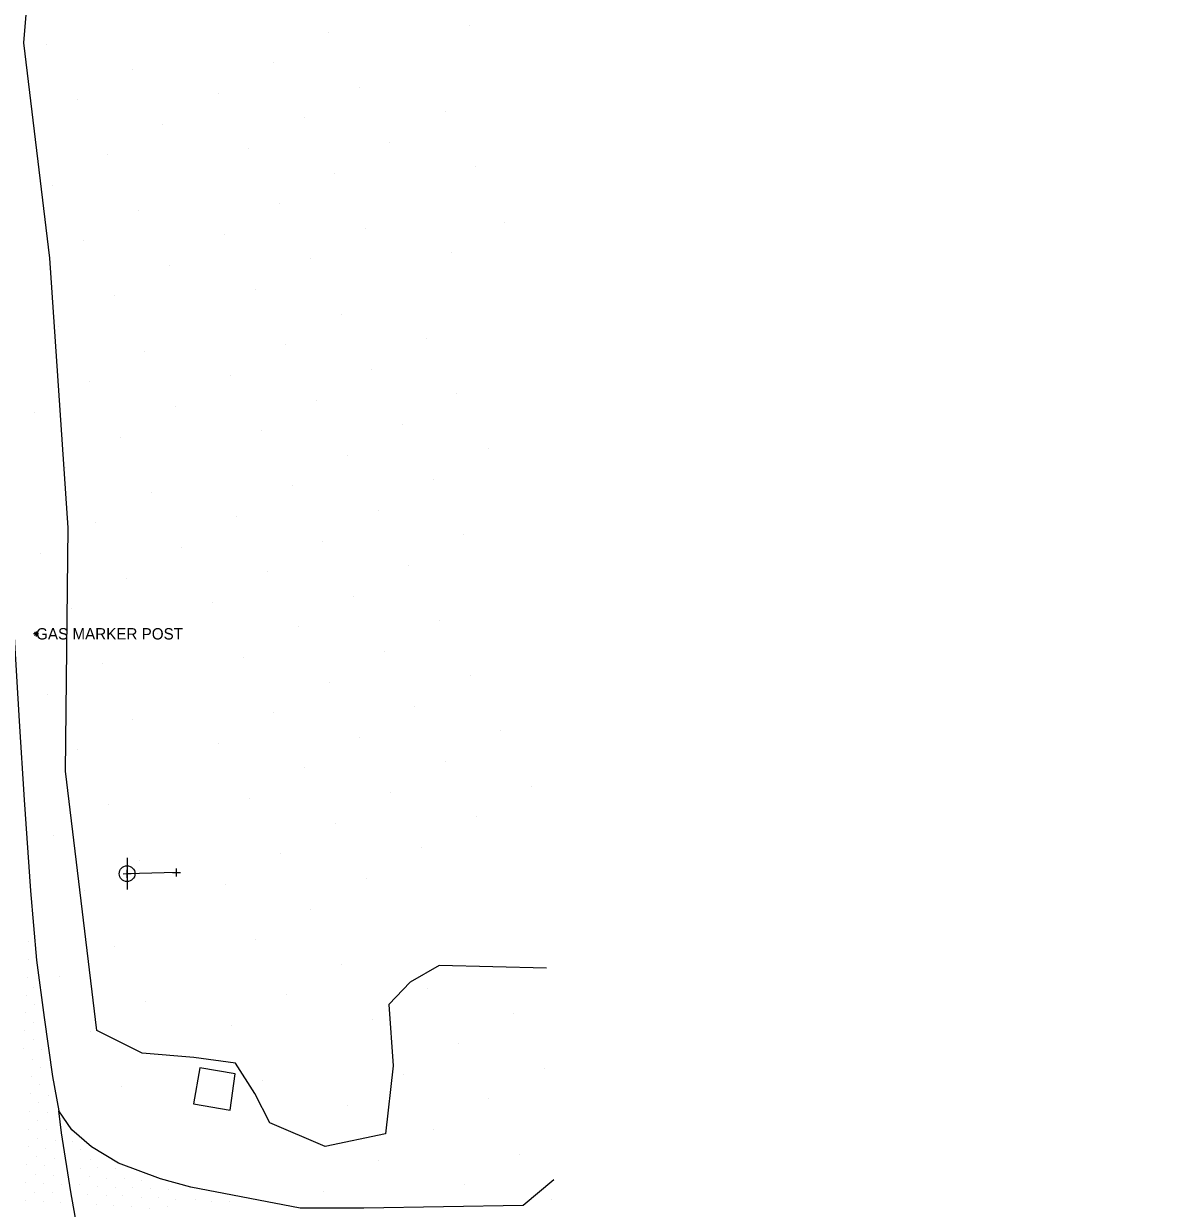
# Model space of a CAD drawing. Extents: x 1733582 to 1734070, y 467256 to 468256.
# Drawn here: x 1733851.7 to 1734031.3, y 467368 to 467555.7 of the extents above; entities that cross this region are included whole.
import ezdxf

# ---------------------------------------------------------------- set-up
doc = ezdxf.new("R2010")
doc.units = 0
for name, color, linetype in [('Default', 7, 'Continuous'), ('S_Ground_LevelString', 7, 'Continuous'), ('S_Ground_SpotElevation', 7, 'Continuous'), ('S_Misc_MiscItems', 7, 'Continuous'), ('S_Roadway_Drive_Paved', 7, 'Continuous'), ('S_Roadway_Edge_Pavement', 7, 'Continuous'), ('S_Survey_Shot', 7, 'Continuous'), ('S_Text', 7, 'Continuous'), ('S_Trees_Bush_Line', 7, 'Continuous'), ('S_Utilities_GuyWire3', 7, 'Continuous'), ('S_Utilities_Pole_Power', 7, 'Continuous')]:
    doc.layers.add(name, color=color, linetype=linetype)

# ---------------------------------------------------------------- blocks, each defined once
blk = doc.blocks.new('POINT_DISPLAY')
at = {"layer": 'Default'}
blk.add_line((0, 0), (0, 0), dxfattribs=at)

msp = doc.modelspace()

# ---------------------------------------------------------------- linework, layer by layer
at = {"layer": 'S_Ground_LevelString'}
msp.add_lwpolyline([(1733885.2, 467389.3), (1733879.61, 467390.29), (1733878.63, 467384.56), (1733884.43, 467383.56), (1733885.2, 467389.3)], dxfattribs=at)
at = {"layer": 'S_Misc_MiscItems'}
for p, q in [((1733854.07, 467459.02), (1733853.28, 467459.02)), ((1733853.94, 467458.75), (1733853.41, 467459.28)), ((1733853.94, 467459.28), (1733853.41, 467458.75)), ((1733853.68, 467459.41), (1733853.68, 467458.62))]:
    msp.add_line(p, q, dxfattribs=at)
at = {"layer": 'S_Roadway_Drive_Paved'}
msp.add_lwpolyline([(1733935.69, 467372.52), (1733930.85, 467368.48), (1733905.61, 467368.04), (1733895.53, 467368.04), (1733878.21, 467371.35), (1733873.41, 467372.67), (1733866.75, 467375.19), (1733862.45, 467377.76), (1733859.35, 467380.43), (1733857.26, 467383.48)], dxfattribs=at)
at = {"layer": 'S_Roadway_Edge_Pavement'}
for points in [[(1733844.86, 467556.39), (1733844.81, 467544.75), (1733845.09, 467538.7), (1733845.54, 467531.94), (1733846.9, 467523.49), (1733847.19, 467517.58), (1733848.33, 467507.5), (1733848.82, 467501.93), (1733849.37, 467495.51), (1733849.25, 467489.25), (1733848.88, 467482.09), (1733849.39, 467470.34), (1733850.19, 467458.56), (1733850.99, 467445.17), (1733851.8, 467432.75), (1733852.77, 467418.3), (1733853.74, 467407.33), (1733854.98, 467398.25), (1733856.26, 467388.9), (1733857.26, 467383.48)], [(1733865.37, 467333.83), (1733864.02, 467343.01), (1733861.67, 467356.68), (1733859.17, 467370.65), (1733857.7, 467379.97), (1733857.26, 467383.48)]]:
    msp.add_lwpolyline(points, dxfattribs=at)
at = {"layer": 'S_Survey_Shot'}
for p, q in [((1733867.46, 467421.02), (1733868.73, 467421.03)), ((1733868.1, 467420.39), (1733868.09, 467421.66)), ((1733868.09, 467421.02), (1733868.09, 467421.02)), ((1733875.28, 467421.2), (1733876.55, 467421.2)), ((1733875.92, 467420.56), (1733875.91, 467421.84)), ((1733875.92, 467421.2), (1733875.92, 467421.2))]:
    msp.add_line(p, q, dxfattribs=at)
at = {"layer": 'S_Trees_Bush_Line'}
for points in [[(1733870.48, 467392.59), (1733863.3, 467396.17), (1733858.35, 467437.26), (1733858.75, 467475.79), (1733855.85, 467518.53), (1733851.72, 467552.62), (1733854.12, 467581.29), (1733854.36, 467608.62), (1733855, 467643.49), (1733857.77, 467661.2), (1733862.91, 467670.92), (1733887.36, 467667.82), (1733924.77, 467650.09), (1734031.29, 467613.46)], [(1733934.51, 467406.04), (1733917.54, 467406.47), (1733912.96, 467403.85), (1733909.54, 467400.28), (1733910.22, 467390.61), (1733909.03, 467379.81), (1733899.45, 467377.84), (1733890.7, 467381.58), (1733888.33, 467386.19), (1733885.25, 467391.01), (1733878.64, 467391.93), (1733870.48, 467392.59)]]:
    msp.add_lwpolyline(points, dxfattribs=at)
at = {"layer": 'S_Utilities_GuyWire3'}
msp.add_lwpolyline([(1733875.92, 467421.2), (1733868.09, 467421.02)], dxfattribs=at)
at = {"layer": 'S_Utilities_Pole_Power'}
msp.add_line((1733868.09, 467423.52), (1733868.09, 467418.53), dxfattribs=at)
msp.add_circle((1733868.09, 467421.02), 1.25, dxfattribs=at)

# ---------------------------------------------------------------- block references
at = {"layer": 'S_Ground_SpotElevation'}
for p in [(1733899.99, 467554.33), (1733922.33, 467555.32), (1733855.32, 467552.34), (1733868.92, 467548.47), (1733891.26, 467549.46), (1733882.52, 467544.6), (1733904.86, 467545.59), (1733860.18, 467543.61), (1733896.12, 467540.73), (1733918.46, 467541.72), (1733873.78, 467539.73), (1733887.38, 467535.86), (1733909.72, 467536.86), (1733865.05, 467534.87), (1733900.99, 467531.99), (1733923.32, 467532.98), (1733856.31, 467530), (1733869.91, 467526.13), (1733892.25, 467527.13), (1733927.91, 467524.24), (1733883.51, 467522.26), (1733905.85, 467523.25), (1733861.17, 467521.27), (1733897.11, 467518.39), (1733919.45, 467519.38), (1733874.78, 467517.4), (1733866.04, 467512.53), (1733888.38, 467513.52), (1733901.98, 467509.65), (1733857.3, 467507.67), (1733915.58, 467505.78), (1733870.9, 467503.79), (1733893.24, 467504.79), (1733884.51, 467499.92), (1733906.84, 467500.92), (1733862.17, 467498.93), (1733898.11, 467496.05), (1733920.31, 467497.14), (1733853.43, 467494.06), (1733875.77, 467495.06), (1733911.71, 467492.18), (1733867.03, 467490.19), (1733889.37, 467491.19), (1733925.31, 467488.31), (1733902.97, 467487.31), (1733858.29, 467485.33), (1733916.57, 467483.44), (1733871.9, 467481.46), (1733894.24, 467482.45), (1733885.5, 467477.58), (1733907.84, 467478.58), (1733863.16, 467476.59), (1733899.1, 467473.71), (1733921.44, 467474.71), (1733854.42, 467471.73), (1733876.76, 467472.72), (1733912.7, 467469.84), (1733868.02, 467467.85), (1733890.36, 467468.85), (1733881.63, 467463.98), (1733903.97, 467464.98), (1733859.29, 467462.99), (1733895.23, 467460.11), (1733917.57, 467461.1), (1733872.89, 467459.12), (1733908.83, 467456.24), (1733886.49, 467455.25), (1733864.15, 467454.25), (1733900.09, 467451.37), (1733922.43, 467452.37), (1733855.42, 467449.39), (1733913.7, 467447.5), (1733869.02, 467445.52), (1733891.36, 467446.51), (1733927.3, 467443.63), (1733882.62, 467441.64), (1733904.96, 467442.64), (1733860.28, 467440.65), (1733896.22, 467437.77), (1733918.56, 467438.76), (1733909.82, 467433.9), (1733932.16, 467434.89), (1733865.15, 467431.91), (1733887.48, 467432.91), (1733923.43, 467430.03), (1733901.09, 467429.03), (1733856.41, 467427.05), (1733914.69, 467425.16), (1733870.01, 467423.18), (1733892.35, 467424.17), (1733883.61, 467419.3), (1733905.95, 467420.3), (1733861.27, 467418.31), (1733897.21, 467415.43), (1733852.45, 467410.34), (1733866.14, 467409.57), (1733888.48, 467410.57), (1733852.44, 467407.39), (1733902.08, 467406.7), (1733852.32, 467404.52), (1733857.4, 467404.71), (1733853.29, 467403.07), (1733893.34, 467401.83), (1733915.68, 467402.82), (1733852.18, 467401.75), (1733853.45, 467400.36), (1733871, 467400.84), (1733852.04, 467398.97), (1733929.28, 467398.95), (1733851.9, 467396.17), (1733853.23, 467397.49), (1733884.61, 467396.97), (1733906.94, 467397.96), (1733853.21, 467394.73), (1733862.27, 467395.97), (1733851.74, 467393.38), (1733854.56, 467393.19), (1733920.55, 467394.09), (1733853.06, 467391.67), (1733875.87, 467392.1), (1733852.92, 467388.96), (1733854.41, 467390.39), (1733911.81, 467389.22), (1733934.15, 467390.22), (1733854.2, 467387.65), (1733867.13, 467387.24), (1733889.47, 467388.23), (1733852.74, 467386.24), (1733855.64, 467385.92), (1733925.41, 467385.35), (1733852.68, 467383.3), (1733854.09, 467384.82), (1733855.44, 467383.14), (1733903.07, 467384.36), (1733853.84, 467381.96), (1733852.51, 467380.52), (1733855.31, 467380.52), (1733916.67, 467380.49), (1733852.4, 467377.74), (1733853.84, 467379.14), (1733855.23, 467377.48), (1733856.69, 467378.84), (1733859.49, 467378.67), (1733853.72, 467376.21), (1733856.53, 467375.97), (1733860.75, 467377.3), (1733862.22, 467375.81), (1733907.94, 467375.62), (1733930.28, 467376.61), (1733852.2, 467374.94), (1733855.03, 467374.83), (1733860.65, 467374.34), (1733863.46, 467374.41), (1733866.27, 467374.31), (1733852.03, 467372.13), (1733853.61, 467373.4), (1733854.93, 467371.91), (1733856.42, 467373.29), (1733857.75, 467371.81), (1733862.07, 467373.04), (1733864.9, 467372.78), (1733867.71, 467372.67), (1733870.45, 467372.4), (1733853.44, 467370.53), (1733856.29, 467370.48), (1733860.54, 467371.73), (1733861.87, 467370.22), (1733863.35, 467371.51), (1733864.76, 467370), (1733866.26, 467371.34), (1733867.44, 467369.99), (1733868.98, 467371.26), (1733871.84, 467371.12), (1733874.62, 467371), (1733899.2, 467370.76), (1733921.54, 467371.75), (1733851.95, 467369.27), (1733854.8, 467369.13), (1733857.57, 467368.99), (1733863.26, 467368.59), (1733865.96, 467368.51), (1733868.83, 467368.37), (1733870.39, 467369.8), (1733871.68, 467368.06), (1733873.08, 467369.72), (1733874.49, 467368.26), (1733875.76, 467369.46), (1733878.89, 467369.37), (1733881.54, 467369.03), (1733884.32, 467369.16), (1733935.33, 467369.4)]:
    msp.add_blockref('POINT_DISPLAY', p, dxfattribs=at)

# ---------------------------------------------------------------- texts
at = {"layer": 'S_Text'}
msp.add_text('GAS MARKER POST', height=1.8, dxfattribs=at).set_placement((1733853.68, 467458.12))

doc.saveas('drawing.dxf')
